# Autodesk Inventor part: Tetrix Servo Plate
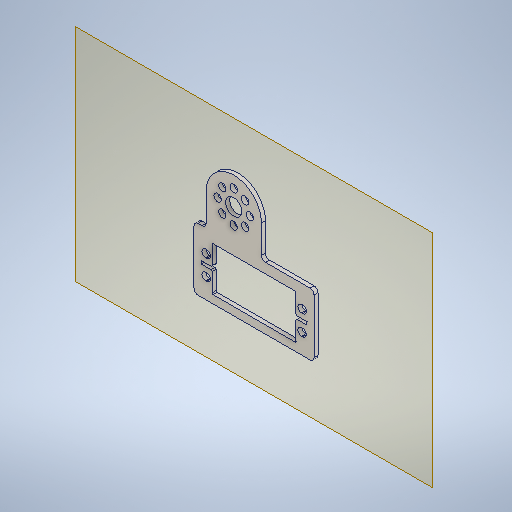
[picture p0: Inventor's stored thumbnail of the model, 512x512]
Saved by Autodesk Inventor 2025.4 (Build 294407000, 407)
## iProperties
Created: 2021-10
Part Number: Tetrix Servo Plate
Material: Genérico
Document SubType Name: Modeling
Designer: usuario
Density: 1 g/cm^3
Appearance: Valor por defecto
Author: usuario
Sending System: SolidWorks 2016
Last Author: LENOVO
Last Saved: 2021-10-26
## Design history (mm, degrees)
feature "Boss-Extrude1"
node "Plane1"
node "Sólido1"
